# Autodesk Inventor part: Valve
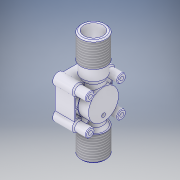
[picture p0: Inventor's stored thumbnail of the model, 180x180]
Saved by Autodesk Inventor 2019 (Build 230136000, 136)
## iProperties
Created: 2019-04
Part Number: Valve
Material: Generic
Document SubType Name: Modeling
Designer: Plo
Density: 1 g/cm^3
Appearance: Cool White
Author: Plo
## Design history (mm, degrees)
sketch "Sketch1"
  geometry: C1 r 10 at (0, 0); 1 further point
  constraints: 1 centre point, 1 coincident
  dimensions: "d0" = 20 diameter of C1
extrude "Extrusion1" new body sketch "Sketch1" distance "d1" = 20; taper "d2" = 0 deg
thread "Thread1" dims "d3" = 10, "d4" = 0
sketch "Sketch2"
  geometry: C1 r 7.5 at (0, 0); 1 further point
  constraints: 1 centre point, 1 coincident
  dimensions: "d5" = 15 diameter of C1
extrude "Extrusion2" cut sketch "Sketch2" stored distance "d6" = 20; taper "d7" = 0 deg
sketch "Sketch3"
  geometry: C1 r 9 at (0, 0); 1 further point
  constraints: 1 centre point, 1 coincident
  dimensions: "d8" = 18 diameter of C1
extrude "Extrusion3" join sketch "Sketch3" distance "d9" = 9; taper "d10" = 0 deg
workplane "Work Plane1"
sketch "Sketch4"
  geometry: C1 r 7.5 at (0, 0); 1 further point
  constraints: 1 centre point, 1 coincident
  dimensions: "d12" = 15 diameter of C1
loft "Loft1" sketch "Sketch4" dims "d13" = 0, "d14" = 90 deg, "d15" = 0, "d16" = 90 deg
  node "Edges1"
sketch "Sketch5"
  geometry: L1 (-12, -7.5)-(-12, 7.5) reference; L2 (-12, -8.758)-(-12, 0); L3 (-12, 0)-(-12, 8.758); L4 (-18.242, 15)-(-35.758, 15); L5 (-42, 8.758)-(-42, -8.758); L6 (-12, -8.758)-(-12, 0); L7 (-42, -15)-(-39.5, -15); L8 (-39.5, -15)-(-39.5, -12.5); L9 (-42, -15)-(-39.5, -15); L10 (-12, 0)-(-17, 0); L11 (-27, 15)-(-27, 10); L12 (-12, -15)-(-14.5, -15); L13 (-14.5, -15)-(-14.5, -12.5); L14 (-12, -15)-(-14.5, -15); L15 (-35.758, -15)-(-18.242, -15); L16 (-14.5, -15)-(-12, -15); C1 r 1.5 at (-39.5, -12.5); C2 r 1.5 at (-14.5, -12.5); C3 r 1.5 at (-14.5, 12.5); C4 r 1.5 at (-39.5, 12.5); A1 r 4.5 centre (-39.5, -12.5) between (-42, -8.758) and (-35.758, -15); A2 r 4.5 centre (-14.5, -12.5) between (-18.242, -15) and (-12, -8.758); A3 r 4.5 centre (-14.5, 12.5) between (-12, 8.758) and (-18.242, 15); A4 r 4.5 centre (-39.5, 12.5) between (-35.758, 15) and (-42, 8.758); 2 further points
  constraints: 30 end point, 15 symmetric about line, 12 point on circle, 8 centre point, 4 coincident, 4 perpendicular, 2 collinear, 2 midpoint, 2 point on line, 1 vertical, 6 other
  dimensions: "d35" = 30 distance of L7.start L12.start; "d36" = 2.5 distance of L7.start L7.end; "d37" = 2.5 distance of L7.end L8.end; "d38" = 5 distance of L2.end L10.end; "d39" = 5 distance of L11.start L11.end
extrude "Extrusion5" join sketch "Sketch5" distance "d40" = 15.5; taper "d41" = 0 deg
sketch "Sketch7"
  geometry: C1 r 13.5 at (0, -27); 1 further point
  constraints: 1 centre point
  dimensions: "d42" = 27 diameter of C1
extrude "Extrusion6" cut sketch "Sketch7" distance "d43" = 10; taper "d44" = 0 deg
sketch "Sketch8"
  geometry: C1 r 12 at (0, -27); 1 further point
  constraints: 1 centre point
  dimensions: "d45" = 24 diameter of C1
extrude "Extrusion7" join sketch "Sketch8" distance "d46" = 8; taper "d47" = 0 deg
sketch "Sketch9"
  geometry: L1 (0, 7.5)-(0, -7.5) reference; A1 r 7.5 centre (0, 0) between (0, -7.5) and (0, 7.5) reference; 1 further point
extrude "Extrusion8" join sketch "Sketch9" stored distance "d48" = 8; taper "d49" = 0 deg
sketch "Sketch10"
  geometry: C1 r 3.5 at (12.5, -39.5); C2 r 3.5 at (-12.5, -39.5); C3 r 3.5 at (-12.5, -14.5); C4 r 3.5 at (12.5, -14.5); C5 r 1.5 at (12.5, -39.5) reference; C6 r 1.5 at (12.5, -39.5); C7 r 1.5 at (-12.5, -39.5) reference; C8 r 1.5 at (-12.5, -14.5) reference; C9 r 1.5 at (12.5, -14.5) reference; 5 further points
  constraints: 5 centre point, 5 coincident
  dimensions: "d50" = 7 diameter of C1; "d51" = 7 diameter of C2; "d52" = 7 diameter of C3; "d53" = 7 diameter of C4; "d54" = 3 diameter of C6
extrude "Extrusion9" join sketch "Sketch10" distance "d55" = 10; taper "d56" = 0 deg
sketch "Sketch11"
  geometry: L1 (10.025, -37.025)-(8.485, -35.485); L2 (9.697, -37.404)-(8.124, -35.831); L3 (10.404, -36.697)-(8.831, -35.124); C1 r 1.5 at (12.5, -39.5) reference; C2 r 1.5 at (12.5, -39.5) reference; C3 r 12 at (0, -27) reference; A1 r 12 centre (0, -27) between (-7.5, -17.633) and (7.5, -17.633) reference; A2 r 3.5 centre (12.5, -39.5) between (10.025, -37.025) and (10.404, -36.697) reference; A3 r 12 centre (0, -27) between (7.5, -17.633) and (-7.5, -17.633) reference; 1 further point
  constraints: 6 end point, 6 point on circle, 2 parallel
  dimensions: "d57" = 0.5 distance between parallel lines of L1 L2; "d58" = 0.5 distance between parallel lines of L1 L3
extrude "Extrusion10" join sketch "Sketch11" distance "d59" = 5; taper "d60" = 0 deg
sketch "Sketch12"
  geometry: L1 (-7.5, -17.633)-(-7.5, -12) reference; L2 (-7.5, -12)-(-8.758, -12) reference; L3 (-15, -18.242)-(-15, -35.758) reference; L4 (-8.758, -42)-(8.758, -42) reference; L5 (15, -35.758)-(15, -18.242) reference; L6 (8.758, -12)-(7.5, -12) reference; L7 (7.5, -12)-(7.5, -17.633) reference; L8 (8.831, -35.124)-(10.404, -36.697) reference; L9 (9.697, -37.404)-(8.124, -35.831) reference; L10 (15, -34.601)-(15, -18.242); L11 (14, -34.208)-(14, -19.792); L12 (15, -35.758)-(15, -18.242) reference; L13 (14, -26.921)-(12.5, -26.921); L14 (14, -25.921)-(12.453, -25.921); C1 r 3.5 at (-12.5, -14.5) reference; C2 r 3.5 at (12.5, -14.5) reference; C3 r 3.5 at (-12.5, -39.5) reference; A1 r 12 centre (0, -27) between (8.831, -35.124) and (7.5, -17.633) reference; A2 r 12 centre (0, -27) between (-7.5, -17.633) and (8.124, -35.831) reference; A3 r 4.5 centre (-12.5, -14.5) between (-8.758, -12) and (-15, -18.242) reference; A4 r 4.5 centre (-12.5, -39.5) between (-15, -35.758) and (-8.758, -42) reference; A5 r 4.5 centre (12.5, -39.5) between (8.758, -42) and (15, -35.758) reference; A6 r 4.5 centre (12.5, -14.5) between (15, -18.242) and (8.758, -12) reference; A7 r 3.5 centre (12.5, -39.5) between (9.697, -37.404) and (10.404, -36.697) reference; A8 r 12.5 centre (0, -27) between (9.871, -34.669) and (9.871, -19.331); A9 r 5.5 centre (12.5, -39.5) between (14, -34.208) and (9.871, -34.669); A10 r 5.5 centre (12.5, -14.5) between (9.871, -19.331) and (14, -19.792); 1 further point
  constraints: 8 end point, 8 point on circle, 3 centre point, 2 point on line, 1 parallel
extrude "Extrusion11" cut sketch "Sketch12" distance "d72" = 5; taper "d73" = 0 deg
pattern_circular "Circular Pattern2" dims angle "d75" = 360 deg
pattern_circular "Circular Pattern3" dims angle "d78" = 360 deg
sketch "Sketch13"
  geometry: L1 (0, -12)-(0, -7.5); C1 r 1.5 at (0, -7.5); A1 r 12 centre (0, 0) between (-8.124, -8.831) and (8.124, -8.831) reference; 1 further point
  constraints: 2 end point, 1 centre point, 1 coincident, 1 point on circle, 1 vertical
  dimensions: "d80" = 4.5 distance of L1.start L1.end; "d81" = 3 diameter of C1
extrude "Extrusion12" cut sketch "Sketch13" distance "d82" = 4; taper "d83" = 0 deg
sketch "Sketch14"
  geometry: A1 r 7.5 centre (15.5, -8.758) between (15.5, -1.258) and (15.5, -16.258) reference; 2 further points
  constraints: 1 coincident, 1 vertical alignment, 2 other
workplane "Work Plane3"
sketch "Sketch15"
  geometry: C1 r 9 at (15.5, -8.758); 1 further point
  constraints: 1 centre point, 1 coincident
loft "Loft2" sketch "Sketch15" dims "d85" = 0, "d86" = 90 deg, "d87" = 0, "d88" = 90 deg
sketch "Sketch16"
  geometry: L1 (0, -7.5)-(0, 7.5) reference; A1 r 7.5 centre (0, 0) between (0, -7.5) and (0, 7.5) reference; 1 further point
extrude "Extrusion13" join sketch "Sketch16" stored distance "d89" = 4; taper "d90" = 0 deg
sketch "Sketch17"
  geometry: C1 r 10 at (0, 0); 1 further point
  constraints: 1 centre point, 1 coincident
extrude "Extrusion14" join sketch "Sketch17" distance "d91" = 20; taper "d92" = 0 deg
thread "Thread2" dims "d93" = 10, "d94" = 0
sketch "Sketch18"
  geometry: C1 r 7.5 at (0, 0); 1 further point
  constraints: 1 centre point, 1 coincident
  dimensions: "d95" = 15 diameter of C1
extrude "Extrusion15" cut sketch "Sketch18" distance "d96" = 20; taper "d97" = 0 deg
chamfer "Chamfer1" distance "d98" = 1; stored, may be unused: second distance "d99" = 2, angle "d100" = 45 deg
fillet "Fillet1" dims "d101" = 0.5
chamfer "Chamfer2" distance "d102" = 1; stored, may be unused: second distance "d103" = 2, angle "d104" = 45 deg
body "Solid1"
node "Projected Loop1"
node "Projected Loop2"
node "Projected Loop3"
node "Projected Loop4"
node "Projected Loop5"
other parameters: "d11" = 3, "d66" = 2, "d67" = 2, "d71" = 1, "d84" = 3
